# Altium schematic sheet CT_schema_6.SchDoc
size 277 x 170 mm
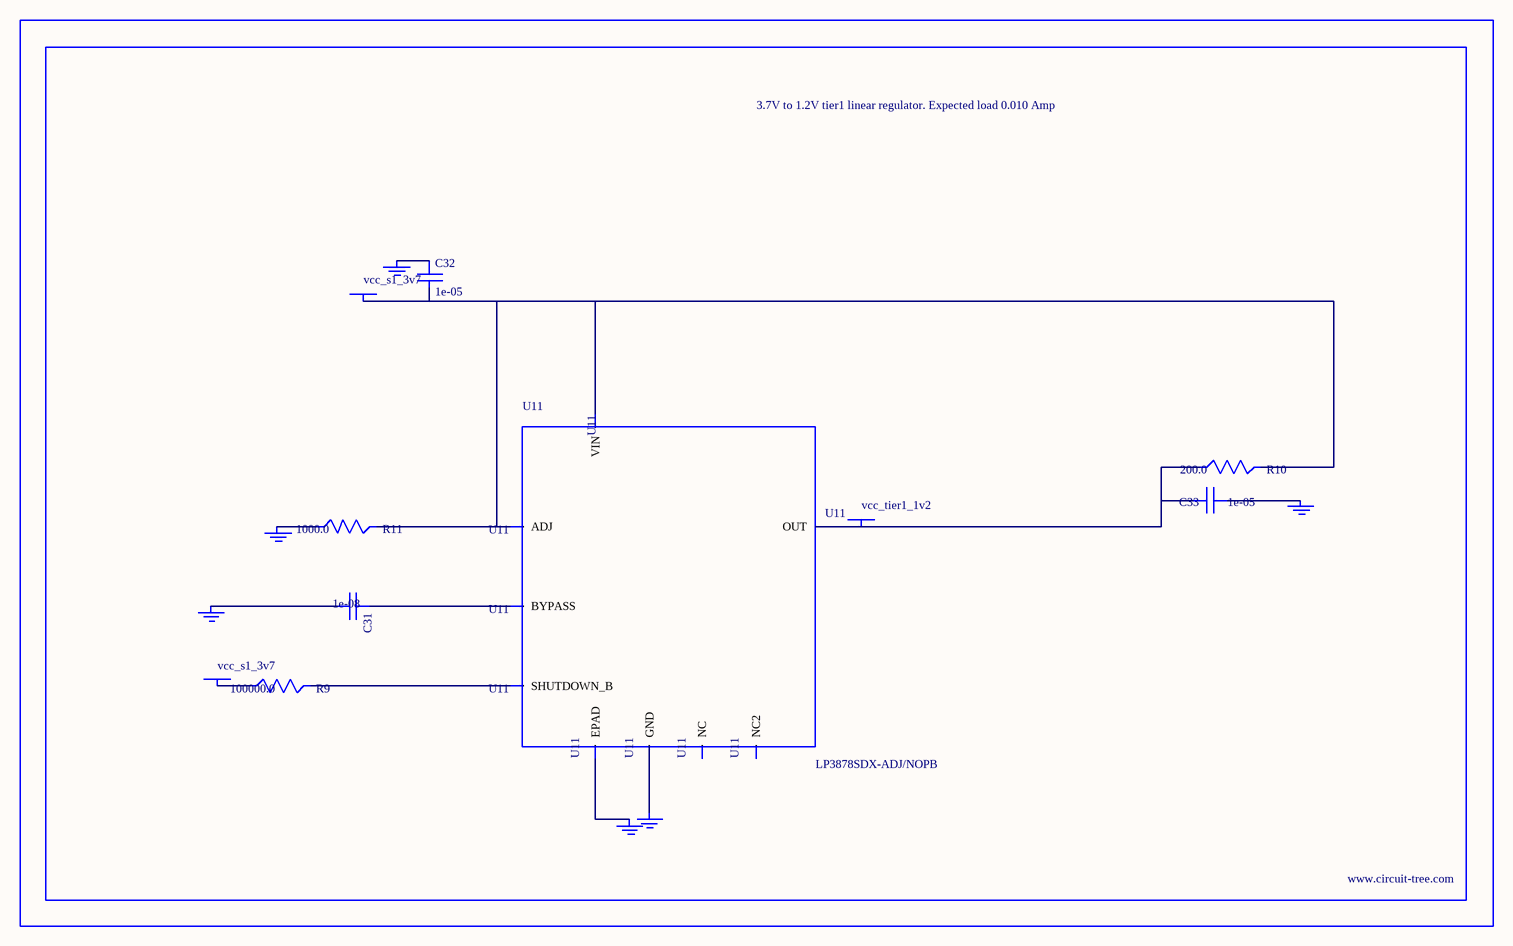
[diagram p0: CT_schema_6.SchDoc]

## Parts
BORDER5  (no value)
C31  1e-08  [C0402]
C32  1e-05  [C0805]
C33  1e-05  [C0805]
GND_INSTANCE_5_0  (no value)
GND_INSTANCE_5_1  (no value)
GND_INSTANCE_5_2  (no value)
GND_INSTANCE_5_3  (no value)
GND_INSTANCE_5_4  (no value)
GND_INSTANCE_5_5  (no value)
POWER_INSTANCE_5_0  vcc_s1_3v7
POWER_INSTANCE_5_1  vcc_s1_3v7
POWER_INSTANCE_5_2  vcc_tier1_1v2
R9  100000.0  [R0603]
R10  200.0  [R0603]
R11  1000.0  [R0603]
U11  LP3878SDX-ADJ/NOPB  [WSON-8]

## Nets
NetC31_1: C31.1 U11.1(BYPASS)
NetC31_2: C31.2 GND_INSTANCE_5_0.0(GND)
NetC32_1: C32.1 GND_INSTANCE_5_1.0(GND)
NetC32_2: C32.2 POWER_INSTANCE_5_0.0(PWR) R10.2 R11.2 U11.4(VIN) U11.6(ADJ)
NetC33_1: C33.1 GND_INSTANCE_5_2.0(GND)
NetC33_2: C33.2 POWER_INSTANCE_5_2.0(PWR) R10.1 U11.5(OUT)
NetGND_INSTANCE_5_3_0: GND_INSTANCE_5_3.0(GND) R11.1
NetGND_INSTANCE_5_4_0: GND_INSTANCE_5_4.0(GND) U11.PAD(EPAD)
NetGND_INSTANCE_5_5_0: GND_INSTANCE_5_5.0(GND) U11.3(GND)
NetPOWER_INSTANCE_5_1_0: POWER_INSTANCE_5_1.0(PWR) R9.1
NetR9_2: R9.2 U11.8(SHUTDOWN_B)

Not connected (* = marked no-connect by the designer): U11 2(NC) 7(NC2)

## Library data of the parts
BORDER5 = BORDER_PAGE5
C31 = C0402C103K3RAC
C32 = C0805C106K8RACTU
C33 = GRM219R60J106ME19D
GND_INSTANCE_5_0-GND_INSTANCE_5_5 = GND
POWER_INSTANCE_5_0-POWER_INSTANCE_5_2 = PWR
R9 = RC0603JR-07100KL
R10 = RC0603JR-07200RL
R11 = RC0603JR-071KL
